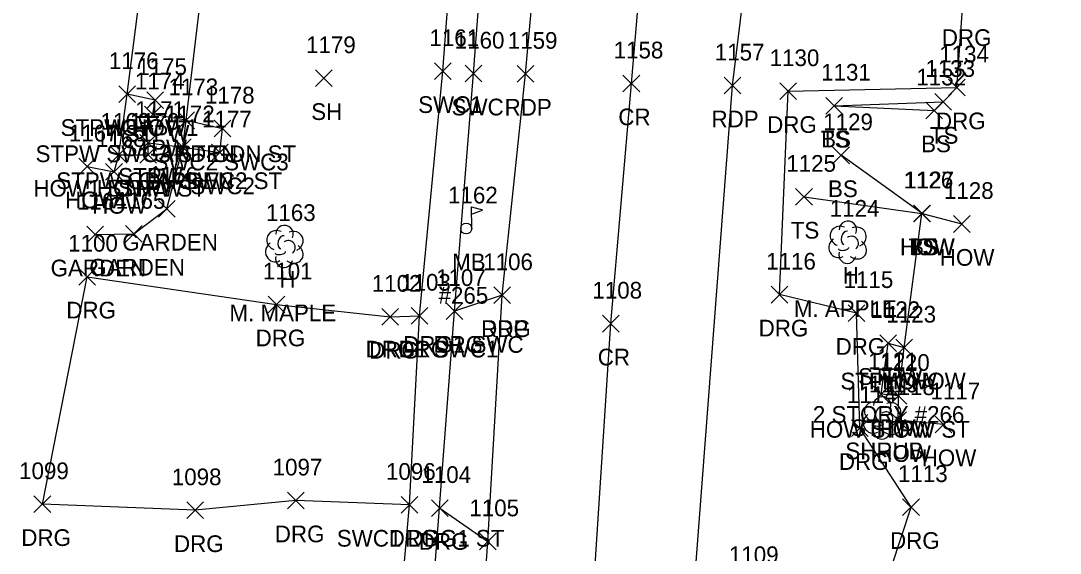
# Model space of a CAD drawing. Extents: x 1653908 to 1654393, y 539913 to 544256.
# Drawn here: x 1653952.4 to 1654076.9, y 541152.6 to 541216.3 of the extents above; entities that cross this region are included whole.
import ezdxf

# ---------------------------------------------------------------- set-up
doc = ezdxf.new("R2010")
doc.units = 0
for name, color, linetype in [('L_A', 7, 'Continuous'), ('L_C', 7, 'Continuous'), ('L_I', 7, 'Continuous'), ('L_TIC', 7, 'Continuous'), ('LAPB', 7, 'Continuous'), ('LBC', 7, 'Continuous'), ('LBF', 7, 'Continuous'), ('LELB', 7, 'Continuous'), ('LMB', 7, 'Continuous'), ('LSH', 7, 'Continuous'), ('LTD', 7, 'Continuous'), ('P_A', 7, 'Continuous'), ('P_I', 7, 'Continuous'), ('P_TIC', 7, 'Continuous'), ('PET', 7, 'Continuous'), ('PRC', 7, 'Continuous'), ('R_A', 7, 'Continuous'), ('R_I', 7, 'Continuous'), ('R_TIC', 7, 'Continuous'), ('RDG', 7, 'Continuous'), ('RSW', 7, 'Continuous')]:
    doc.layers.add(name, color=color, linetype=linetype)

msp = doc.modelspace()

# ---------------------------------------------------------------- linework, layer by layer
at = {"layer": 'L_TIC'}
for points in [[(1653987.74, 541208.42), (1653989.74, 541210.42)], [(1653989.74, 541208.42), (1653987.74, 541210.42)], [(1653964.17, 541206.51), (1653966.17, 541208.51)], [(1653966.17, 541206.51), (1653964.17, 541208.51)], [(1653964.17, 541206.51), (1653966.17, 541208.51)], [(1653966.17, 541206.51), (1653964.17, 541208.51)], [(1653967.52, 541205.8), (1653969.52, 541207.8)], [(1653969.52, 541205.8), (1653967.52, 541207.8)], [(1654061.87, 541205.58), (1654063.87, 541207.58)], [(1654063.87, 541205.58), (1654061.87, 541207.58)], [(1654048.82, 541205.13), (1654050.82, 541207.13)], [(1654050.82, 541205.13), (1654048.82, 541207.13)], [(1654048.82, 541205.13), (1654050.82, 541207.13)], [(1654050.82, 541205.13), (1654048.82, 541207.13)], [(1654060.79, 541204.56), (1654062.79, 541206.56)], [(1654062.79, 541204.56), (1654060.79, 541206.56)], [(1653967.24, 541204.08), (1653969.24, 541206.08)], [(1653969.24, 541204.08), (1653967.24, 541206.08)], [(1653971.26, 541203.38), (1653973.26, 541205.38)], [(1653973.26, 541203.38), (1653971.26, 541205.38)], [(1653971.26, 541203.38), (1653973.26, 541205.38)], [(1653973.26, 541203.38), (1653971.26, 541205.38)], [(1653966.71, 541200.67), (1653968.71, 541202.67)], [(1653968.71, 541200.67), (1653966.71, 541202.67)], [(1653970.84, 541200.15), (1653972.84, 541202.15)], [(1653972.84, 541200.15), (1653970.84, 541202.15)], [(1653970.84, 541200.15), (1653972.84, 541202.15)], [(1653972.84, 541200.15), (1653970.84, 541202.15)], [(1653963.17, 541199.25), (1653965.17, 541201.25)], [(1653965.17, 541199.25), (1653963.17, 541201.25)], [(1653963.17, 541199.25), (1653965.17, 541201.25)], [(1653965.17, 541199.25), (1653963.17, 541201.25)], [(1653966.71, 541199.25), (1653968.71, 541201.25)], [(1653968.71, 541199.25), (1653966.71, 541201.25)], [(1654049.64, 541199.19), (1654051.64, 541201.19)], [(1654051.64, 541199.19), (1654049.64, 541201.19)], [(1653959.38, 541197.85), (1653961.38, 541199.85)], [(1653961.38, 541197.85), (1653959.38, 541199.85)], [(1653962.61, 541197.2), (1653964.61, 541199.2)], [(1653964.61, 541197.2), (1653962.61, 541199.2)], [(1654045.21, 541194.22), (1654047.21, 541196.22)], [(1654047.21, 541194.22), (1654045.21, 541196.22)], [(1653968.93, 541192.79), (1653970.93, 541194.79)], [(1653970.93, 541192.79), (1653968.93, 541194.79)], [(1654059.31, 541192.23), (1654061.31, 541194.23)], [(1654061.31, 541192.23), (1654059.31, 541194.23)], [(1654059.31, 541192.23), (1654061.31, 541194.23)], [(1654061.31, 541192.23), (1654059.31, 541194.23)], [(1654059.35, 541192.24), (1654061.35, 541194.24)], [(1654061.35, 541192.24), (1654059.35, 541194.24)], [(1654059.35, 541192.24), (1654061.35, 541194.24)], [(1654061.35, 541192.24), (1654059.35, 541194.24)], [(1654064.09, 541190.97), (1654066.09, 541192.97)], [(1654066.09, 541190.97), (1654064.09, 541192.97)], [(1653960.35, 541189.7), (1653962.35, 541191.7)], [(1653962.35, 541189.7), (1653960.35, 541191.7)], [(1653964.98, 541189.79), (1653966.98, 541191.79)], [(1653966.98, 541189.79), (1653964.98, 541191.79)], [(1654055.29, 541176.71), (1654057.29, 541178.71)], [(1654057.29, 541176.71), (1654055.29, 541178.71)], [(1654057.19, 541176.17), (1654059.19, 541178.17)], [(1654059.19, 541176.17), (1654057.19, 541178.17)], [(1654057.19, 541176.17), (1654059.19, 541178.17)], [(1654059.19, 541176.17), (1654057.19, 541178.17)], [(1654054.45, 541170.58), (1654056.45, 541172.58)], [(1654056.45, 541170.58), (1654054.45, 541172.58)], [(1654056.52, 541170.39), (1654058.52, 541172.39)], [(1654058.52, 541170.39), (1654056.52, 541172.39)], [(1654056.52, 541170.39), (1654058.52, 541172.39)], [(1654058.52, 541170.39), (1654056.52, 541172.39)], [(1654056.49, 541167.49), (1654058.49, 541169.49)], [(1654058.49, 541167.49), (1654056.49, 541169.49)], [(1654061.91, 541166.98), (1654063.91, 541168.98)], [(1654063.91, 541166.98), (1654061.91, 541168.98)]]:
    msp.add_lwpolyline(points, dxfattribs=at)
at = {"layer": 'LAPB'}
for points in [[(1653972.26, 541204.38), (1653975.07, 541228.23), (1653966.12, 541229.53)], [(1653961.35, 541190.7), (1653965.98, 541190.79), (1653969.93, 541193.79), (1653971.84, 541201.15)]]:
    msp.add_lwpolyline(points, dxfattribs=at)
at = {"layer": 'LBC'}
for points in [[(1653960.38, 541198.85), (1653963.61, 541198.2), (1653964.17, 541200.25), (1653965.17, 541207.51), (1653967.38, 541224.57)], [(1654062.91, 541167.98), (1654057.49, 541168.49), (1654057.52, 541171.39), (1654058.19, 541177.17), (1654060.31, 541193.23), (1654060.35, 541193.24), (1654065.09, 541191.97)]]:
    msp.add_lwpolyline(points, dxfattribs=at)
at = {"layer": 'LBF'}
for points in [[(1653964.17, 541200.25), (1653967.71, 541200.25), (1653967.71, 541201.67), (1653971.84, 541201.15), (1653972.26, 541204.38), (1653968.24, 541205.08), (1653968.52, 541206.8), (1653965.17, 541207.51)], [(1654057.52, 541171.39), (1654055.45, 541171.58), (1654056.29, 541177.71), (1654058.19, 541177.17)]]:
    msp.add_lwpolyline(points, dxfattribs=at)
at = {"layer": 'LELB'}
for points in [[(1654049.82, 541206.13), (1654062.87, 541206.58)], [(1654049.82, 541206.13), (1654061.79, 541205.56)], [(1654060.35, 541193.24), (1654050.64, 541200.19)], [(1654046.21, 541195.22), (1654060.31, 541193.23)]]:
    msp.add_lwpolyline(points, dxfattribs=at)
at = {"layer": 'LMB'}
for p, q in [((1654006.43, 541191.44), (1654006.42, 541194.04)), ((1654006.42, 541194.03), (1654007.71, 541193.65)), ((1654006.42, 541193.13), (1654007.71, 541193.64)), ((1654005.77, 541191.43), (1654005.77, 541191.43))]:
    msp.add_line(p, q, dxfattribs=at)
msp.add_circle((1654005.77, 541191.43), 0.656, dxfattribs=at)
at = {"layer": 'LSH'}
msp.add_line((1654055.53, 541168.81), (1654055.53, 541168.81), dxfattribs=at)
msp.add_line((1654055.53, 541168.81), (1654055.53, 541168.81), dxfattribs=at)
msp.add_arc((1654055.58, 541170.25), 1.05, 335.5272, 180.9563, dxfattribs=at)
for centre, major_axis, ratio, start_param, end_param in [((1654054.74, 541169.48), (1.21, -0.51), 0.895232, 1.570796, 4.712389), ((1654056.57, 541169.4), (-1.14, -0.48), 0.949671, 1.570796, 4.712389), ((1654054.45, 541168.11), (0.58, -1.04), 0.959034, 3.141593, 6.283185), ((1654055.32, 541169.27), (-0.208, -0.792), 0.645439, 3.141593, 6.283185), ((1654056.03, 541168.65), (-0.5, 0.667), 0.989748, 3.141593, 6.283185), ((1654055.08, 541168.06), (-0.625, -0.083), 0.423636, 0, 3.141593), ((1654056.53, 541167.98), (-1.09, 0.79), 0.841452, 1.570796, 4.712389), ((1654055.53, 541167.31), (0.26, 1.06), 0.942809, 1.570796, 4.712389)]:
    msp.add_ellipse(centre, major_axis=major_axis, ratio=ratio, start_param=start_param, end_param=end_param, dxfattribs=at)
at = {"layer": 'LTD'}
for p, q in [((1653983.98, 541189.33), (1653983.98, 541189.33)), ((1653983.98, 541189.33), (1653983.98, 541189.33)), ((1654051.41, 541189.84), (1654051.41, 541189.84)), ((1654051.41, 541189.84), (1654051.41, 541189.84))]:
    msp.add_line(p, q, dxfattribs=at)
for centre in [(1653984.02, 541190.76), (1654051.46, 541191.27)]:
    msp.add_arc(centre, 1.05, 335.5272, 180.9563, dxfattribs=at)
for centre, major_axis, ratio, start_param, end_param in [((1653983.18, 541189.99), (1.21, -0.51), 0.895232, 1.570796, 4.712389), ((1654050.62, 541190.5), (1.21, -0.51), 0.895232, 1.570796, 4.712389), ((1654052.45, 541190.42), (-1.14, -0.48), 0.949671, 1.570796, 4.712389), ((1653983.77, 541189.78), (-0.208, -0.792), 0.645439, 3.141593, 6.283185), ((1653984.48, 541189.16), (-0.5, 0.667), 0.989748, 3.141593, 6.283185), ((1653985.02, 541189.91), (-1.14, -0.48), 0.949671, 1.570796, 4.712389), ((1654050.33, 541189.13), (0.58, -1.04), 0.959034, 3.141593, 6.283185), ((1654051.2, 541190.3), (-0.208, -0.792), 0.645439, 3.141593, 6.283185), ((1654051.91, 541189.67), (-0.5, 0.667), 0.989748, 3.141593, 6.283185), ((1653982.89, 541188.62), (0.58, -1.04), 0.959034, 3.141593, 6.283185), ((1653984.98, 541188.49), (-1.09, 0.79), 0.841452, 1.570796, 4.712389), ((1654050.95, 541189.09), (-0.625, -0.083), 0.423636, 0, 3.141593), ((1654052.41, 541189), (-1.09, 0.79), 0.841452, 1.570796, 4.712389), ((1653983.98, 541187.83), (0.26, 1.06), 0.942809, 1.570796, 4.712389), ((1653983.52, 541188.58), (-0.625, -0.083), 0.423636, 0, 3.141593), ((1654051.41, 541188.34), (0.26, 1.06), 0.942809, 1.570796, 4.712389)]:
    msp.add_ellipse(centre, major_axis=major_axis, ratio=ratio, start_param=start_param, end_param=end_param, dxfattribs=at)
at = {"layer": 'P_TIC'}
for points in [[(1654011.88, 541208.94), (1654013.88, 541210.94)], [(1654013.88, 541208.94), (1654011.88, 541210.94)], [(1654024.54, 541207.79), (1654026.54, 541209.79)], [(1654026.54, 541207.79), (1654024.54, 541209.79)], [(1654036.66, 541207.54), (1654038.66, 541209.54)], [(1654038.66, 541207.54), (1654036.66, 541209.54)], [(1654009.07, 541182.44), (1654011.07, 541184.44)], [(1654011.07, 541182.44), (1654009.07, 541184.44)], [(1654022.08, 541179.04), (1654024.08, 541181.04)], [(1654024.08, 541179.04), (1654022.08, 541181.04)], [(1654007.35, 541152.98), (1654009.35, 541154.98)], [(1654009.35, 541152.98), (1654007.35, 541154.98)]]:
    msp.add_lwpolyline(points, dxfattribs=at)
at = {"layer": 'PET'}
for points in [[(1654002.71, 541022.85), (1654002.8, 541044.57), (1654003.39, 541071.89), (1654004.24, 541078.69), (1654006.74, 541130.14), (1654008.35, 541153.98), (1654010.07, 541183.44), (1654012.88, 541209.94), (1654016.45, 541249.52), (1654022.91, 541308.12), (1654024.64, 541328.52), (1654031.79, 541410), (1654035.81, 541442.82), (1654037.01, 541460.37), (1654040.04, 541491.49), (1654045.58, 541525.89), (1654049.59, 541568.11), (1654053.33, 541590.16), (1654054.27, 541598.35), (1654062.59, 541587.52), (1654071.87, 541577.06), (1654070.19, 541559.91), (1654067.66, 541531.5), (1654064.32, 541497.28)], [(1654026.62, 541021.77), (1654028.54, 541070.24), (1654031.49, 541127.98), (1654037.66, 541208.54), (1654042.53, 541248.32), (1654044.37, 541265.21), (1654043.73, 541271.44), (1654047, 541298.33), (1654052.52, 541346.47), (1654054.45, 541365.83), (1654058.25, 541433.29), (1654064.32, 541497.28)]]:
    msp.add_lwpolyline(points, dxfattribs=at)
at = {"layer": 'PRC'}
msp.add_lwpolyline([(1654015.22, 541022.42), (1654016.68, 541078.09), (1654019.78, 541129.03), (1654023.08, 541180.04), (1654025.54, 541208.79), (1654028.97, 541248.66), (1654033.81, 541299.54), (1654044.55, 541409.64), (1654048.4, 541449.61), (1654049.07, 541458.74), (1654052.54, 541493.4), (1654055.94, 541523.17), (1654060.18, 541564.47), (1654062.59, 541587.52)], dxfattribs=at)
at = {"layer": 'R_TIC'}
for points in [[(1654001.98, 541209.26), (1654003.98, 541211.26)], [(1654003.98, 541209.26), (1654001.98, 541211.26)], [(1654005.66, 541208.97), (1654007.66, 541210.97)], [(1654007.66, 541208.97), (1654005.66, 541210.97)], [(1654043.31, 541206.87), (1654045.31, 541208.87)], [(1654045.31, 541206.87), (1654043.31, 541208.87)], [(1654063.52, 541207.31), (1654065.52, 541209.31)], [(1654065.52, 541207.31), (1654063.52, 541209.31)], [(1653971.26, 541203.38), (1653973.26, 541205.38)], [(1653973.26, 541203.38), (1653971.26, 541205.38)], [(1653975.61, 541202.39), (1653977.61, 541204.39)], [(1653977.61, 541202.39), (1653975.61, 541204.39)], [(1653975.61, 541202.39), (1653977.61, 541204.39)], [(1653977.61, 541202.39), (1653975.61, 541204.39)], [(1653970.84, 541200.15), (1653972.84, 541202.15)], [(1653972.84, 541200.15), (1653970.84, 541202.15)], [(1653975.27, 541199.53), (1653977.27, 541201.53)], [(1653977.27, 541199.53), (1653975.27, 541201.53)], [(1653959.41, 541184.66), (1653961.41, 541186.66)], [(1653961.41, 541184.66), (1653959.41, 541186.66)], [(1654009.07, 541182.44), (1654011.07, 541184.44)], [(1654011.07, 541182.44), (1654009.07, 541184.44)], [(1654042.29, 541182.51), (1654044.29, 541184.51)], [(1654044.29, 541182.51), (1654042.29, 541184.51)], [(1653982.07, 541181.33), (1653984.07, 541183.33)], [(1653984.07, 541181.33), (1653982.07, 541183.33)], [(1653995.67, 541179.86), (1653997.67, 541181.86)], [(1653997.67, 541179.86), (1653995.67, 541181.86)], [(1653999.18, 541179.99), (1654001.18, 541181.99)], [(1654001.18, 541179.99), (1653999.18, 541181.99)], [(1653999.18, 541179.99), (1654001.18, 541181.99)], [(1654001.18, 541179.99), (1653999.18, 541181.99)], [(1654003.36, 541180.55), (1654005.36, 541182.55)], [(1654005.36, 541180.55), (1654003.36, 541182.55)], [(1654003.36, 541180.55), (1654005.36, 541182.55)], [(1654005.36, 541180.55), (1654003.36, 541182.55)], [(1654051.51, 541180.31), (1654053.51, 541182.31)], [(1654053.51, 541180.31), (1654051.51, 541182.31)], [(1654051.9, 541166.53), (1654053.9, 541168.53)], [(1654053.9, 541166.53), (1654051.9, 541168.53)], [(1653954.03, 541157.43), (1653956.03, 541159.43)], [(1653956.03, 541157.43), (1653954.03, 541159.43)], [(1653984.37, 541157.87), (1653986.37, 541159.87)], [(1653986.37, 541157.87), (1653984.37, 541159.87)], [(1653998, 541157.35), (1654000, 541159.35)], [(1654000, 541157.35), (1653998, 541159.35)], [(1653998, 541157.35), (1654000, 541159.35)], [(1654000, 541157.35), (1653998, 541159.35)], [(1654001.61, 541156.97), (1654003.61, 541158.97)], [(1654003.61, 541156.97), (1654001.61, 541158.97)], [(1654058.02, 541157.08), (1654060.02, 541159.08)], [(1654060.02, 541157.08), (1654058.02, 541159.08)], [(1653972.31, 541156.7), (1653974.31, 541158.7)], [(1653974.31, 541156.7), (1653972.31, 541158.7)], [(1654007.35, 541152.98), (1654009.35, 541154.98)], [(1654009.35, 541152.98), (1654007.35, 541154.98)]]:
    msp.add_lwpolyline(points, dxfattribs=at)
at = {"layer": 'RDG'}
for points in [[(1654028.54, 541070.24), (1654038.6, 541077.25), (1654059.57, 541076.94), (1654061.03, 541094.58), (1654044.02, 541099.01), (1654043.13, 541126.19), (1654037.88, 541140.53), (1654039.43, 541148.38), (1654055.52, 541147.43), (1654059.02, 541158.08), (1654052.9, 541167.53), (1654052.51, 541181.31), (1654043.29, 541183.51), (1654044.31, 541207.87), (1654064.52, 541208.31), (1654065.22, 541218.28), (1654063.37, 541224.33), (1654050.59, 541229.36), (1654050.9, 541232.24), (1654056.12, 541263.02), (1654051.65, 541275.04), (1654060.14, 541280.34), (1654076.88, 541278.82)], [(1653999, 541158.35), (1653985.37, 541158.87), (1653973.31, 541157.7), (1653955.03, 541158.43), (1653960.41, 541185.66), (1653983.07, 541182.33), (1653996.67, 541180.86), (1654000.18, 541180.99)], [(1654010.07, 541183.44), (1654004.36, 541181.55)], [(1654002.61, 541157.97), (1654008.35, 541153.98)]]:
    msp.add_lwpolyline(points, dxfattribs=at)
at = {"layer": 'RSW'}
for points in [[(1653995.61, 541066.36), (1653991.56, 541066.06), (1653992.58, 541078.58), (1653996.53, 541130.67), (1653999, 541158.35), (1654000.18, 541180.99), (1654002.98, 541210.26), (1654005.98, 541250), (1654010.23, 541310.58)], [(1653995.61, 541066.36), (1653996.52, 541078.59), (1654000.45, 541130.29), (1654004.36, 541181.55), (1654006.66, 541209.97), (1654009.69, 541249.87), (1654014.15, 541310.29), (1654010.23, 541310.58)], [(1653972.26, 541204.38), (1653976.61, 541203.39)], [(1653971.84, 541201.15), (1653976.27, 541200.53), (1653976.61, 541203.39)]]:
    msp.add_lwpolyline(points, dxfattribs=at)

# ---------------------------------------------------------------- texts
at = {"layer": 'L_A'}
for s, p in [('SH', (1653987.22, 541204.42)), ('STPW HOW1', (1653957.22, 541202.51)), ('HOW', (1653962.56, 541202.51)), ('STPW', (1653964.91, 541201.8)), ('TS', (1654048.23, 541201.13)), ('BS', (1654048.26, 541201.13)), ('BS', (1654060.23, 541200.56)), ('TS', (1654061.28, 541201.58)), ('STPW SWC3 ST GDN ST', (1653954.22, 541199.38)), ('STPW', (1653964.63, 541200.08)), ('GARDEN', (1653966.92, 541199.38)), ('STPW GDN SWC2 ST', (1653956.7, 541196.15)), ('STPW', (1653964.11, 541196.67)), ('GARDEN', (1653966.51, 541196.15)), ('HOW1 STPW ST', (1653953.96, 541195.25)), ('HOW', (1653961.56, 541195.25)), ('STPW', (1653964.1, 541195.25)), ('BS', (1654049.08, 541195.19)), ('HOW', (1653957.76, 541193.85)), ('HOW', (1653961, 541193.2)), ('TS', (1654044.62, 541190.22)), ('GARDEN', (1653964.6, 541188.79)), ('HOW', (1654057.7, 541188.23)), ('HOW', (1654057.73, 541188.24)), ('TS', (1654058.72, 541188.23)), ('BS', (1654058.79, 541188.24)), ('HOW', (1654062.47, 541186.97)), ('GARDEN', (1653956.02, 541185.7)), ('GARDEN', (1653960.65, 541185.79)), ('MB', (1654004.08, 541186.43)), ('H', (1653983.41, 541184.33)), ('H', (1654050.84, 541184.84)), ('STPW HOW', (1654050.57, 541172.17)), ('STPW', (1654052.68, 541172.71)), ('HOW', (1654055.58, 541172.17)), ('HOW STPW ST', (1654046.9, 541166.39)), ('STPW', (1654051.85, 541166.58)), ('HOW', (1654054.9, 541166.39)), ('SHRUB', (1654051.16, 541163.81)), ('HOW', (1654054.87, 541163.49)), ('HOW', (1654060.3, 541162.98))]:
    msp.add_text(s, height=2, dxfattribs=at).set_placement(p)
at = {"layer": 'L_C'}
for s, p in [('#265', (1654002.46, 541182.43)), ('M. APPLE', (1654044.99, 541180.84)), ('M. MAPLE', (1653977.43, 541180.33)), ('2 STORY #266', (1654047.27, 541168.17))]:
    msp.add_text(s, height=2, dxfattribs=at).set_placement(p)
at = {"layer": 'L_I'}
for s, p in [('1179', (1653986.6, 541212.42)), ('1176', (1653962.99, 541210.51)), ('1176', (1653962.99, 541210.51)), ('1175', (1653966.39, 541209.8)), ('1133', (1654060.74, 541209.58)), ('1174', (1653966.11, 541208.08)), ('1131', (1654048.26, 541209.13)), ('1131', (1654048.26, 541209.13)), ('1132', (1654059.66, 541208.56)), ('1173', (1653970.13, 541207.38)), ('1173', (1653970.13, 541207.38)), ('1171', (1653966.15, 541204.67)), ('1169', (1653961.99, 541203.25)), ('1169', (1653961.99, 541203.25)), ('1170', (1653965.49, 541203.25)), ('1172', (1653969.71, 541204.15)), ('1172', (1653969.71, 541204.15)), ('1129', (1654048.51, 541203.19)), ('1167', (1653958.2, 541201.85)), ('1168', (1653961.44, 541201.2)), ('1125', (1654044.09, 541198.22)), ('1166', (1653967.7, 541196.79)), ('1126', (1654058.13, 541196.23)), ('1126', (1654058.13, 541196.23)), ('1127', (1654058.22, 541196.24)), ('1127', (1654058.22, 541196.24)), ('1162', (1654003.6, 541194.43)), ('1128', (1654062.96, 541194.97)), ('1164', (1653959.18, 541193.7)), ('1165', (1653963.81, 541193.79)), ('1163', (1653981.8, 541192.33)), ('1124', (1654049.29, 541192.84)), ('1122', (1654054.16, 541180.71)), ('1123', (1654056.07, 541180.17)), ('1123', (1654056.07, 541180.17)), ('1121', (1654053.89, 541174.58)), ('1120', (1654055.31, 541174.39)), ('1120', (1654055.31, 541174.39)), ('1119', (1654053.97, 541171.81)), ('1118', (1654055.93, 541171.49)), ('1117', (1654061.35, 541170.98))]:
    msp.add_text(s, height=2, dxfattribs=at).set_placement(p)
at = {"layer": 'P_A'}
for s, p in [('RDP', (1654010.37, 541204.94)), ('CR', (1654023.98, 541203.79)), ('RDP', (1654035.14, 541203.54)), ('RDP', (1654007.56, 541178.44)), ('CR', (1654021.52, 541175.04))]:
    msp.add_text(s, height=2, dxfattribs=at).set_placement(p)
at = {"layer": 'P_I'}
for s, p in [('1159', (1654010.75, 541212.94)), ('1158', (1654023.42, 541211.79)), ('1157', (1654035.53, 541211.54)), ('1106', (1654007.81, 541186.44)), ('1108', (1654020.88, 541183.04)), ('1105', (1654006.15, 541156.98))]:
    msp.add_text(s, height=2, dxfattribs=at).set_placement(p)
at = {"layer": 'R_A'}
for s, p in [('DRG', (1654062.71, 541213.28)), ('SWC1', (1654000.02, 541205.26)), ('SWC', (1654004.02, 541204.97)), ('DRG', (1654062.01, 541203.31)), ('DRG', (1654041.8, 541202.87)), ('STPW SWC3 ST GDN ST', (1653954.22, 541199.38)), ('SWC2 SWC3', (1653968.33, 541198.39)), ('SWC2 SWC3', (1653968.33, 541198.39)), ('STPW GDN SWC2 ST', (1653956.7, 541196.15)), ('SWC2', (1653972.75, 541195.53)), ('DRG', (1653957.9, 541180.66)), ('DRG', (1654007.56, 541178.44)), ('DRG', (1654040.78, 541178.51)), ('DRG', (1653980.56, 541177.33)), ('DRG1 SWC1', (1653993.73, 541175.99)), ('DRG', (1653994.16, 541175.86)), ('DRG', (1653997.67, 541175.99)), ('DRG1 SWC', (1653998.23, 541176.55)), ('DRG', (1654001.85, 541176.55)), ('DRG', (1654049.99, 541176.31)), ('DRG', (1654050.39, 541162.53)), ('DRG', (1653952.51, 541153.43)), ('DRG', (1653982.86, 541153.87)), ('SWC1 DRG1 ST', (1653990.28, 541153.35)), ('DRG', (1653996.49, 541153.35)), ('DRG', (1653970.79, 541152.7)), ('DRG', (1654000.1, 541152.97)), ('DRG', (1654056.51, 541153.08))]:
    msp.add_text(s, height=2, dxfattribs=at).set_placement(p)
at = {"layer": 'R_I'}
for s, p in [('1161', (1654001.37, 541213.26)), ('1160', (1654004.4, 541212.97)), ('1130', (1654042.1, 541210.87)), ('1134', (1654062.4, 541211.31)), ('1173', (1653970.13, 541207.38)), ('1178', (1653974.49, 541206.39)), ('1178', (1653974.49, 541206.39)), ('1172', (1653969.71, 541204.15)), ('1177', (1653974.15, 541203.53)), ('1100', (1653958.12, 541188.66)), ('1106', (1654007.81, 541186.44)), ('1116', (1654041.68, 541186.51)), ('1101', (1653981.43, 541185.33)), ('1107', (1654002.16, 541184.55)), ('1107', (1654002.16, 541184.55)), ('1102', (1653994.47, 541183.86)), ('1103', (1653997.98, 541183.99)), ('1103', (1653997.98, 541183.99)), ('1115', (1654050.95, 541184.31)), ('1114', (1654051.34, 541170.53)), ('1099', (1653952.25, 541161.43)), ('1098', (1653970.53, 541160.7)), ('1097', (1653982.6, 541161.87)), ('1096', (1653996.17, 541161.35)), ('1096', (1653996.17, 541161.35)), ('1104', (1654000.41, 541160.97)), ('1113', (1654057.46, 541161.08)), ('1105', (1654006.15, 541156.98)), ('1109', (1654037.22, 541151.38))]:
    msp.add_text(s, height=2, dxfattribs=at).set_placement(p)

doc.saveas('drawing.dxf')
